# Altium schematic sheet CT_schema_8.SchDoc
size 274 x 160 mm
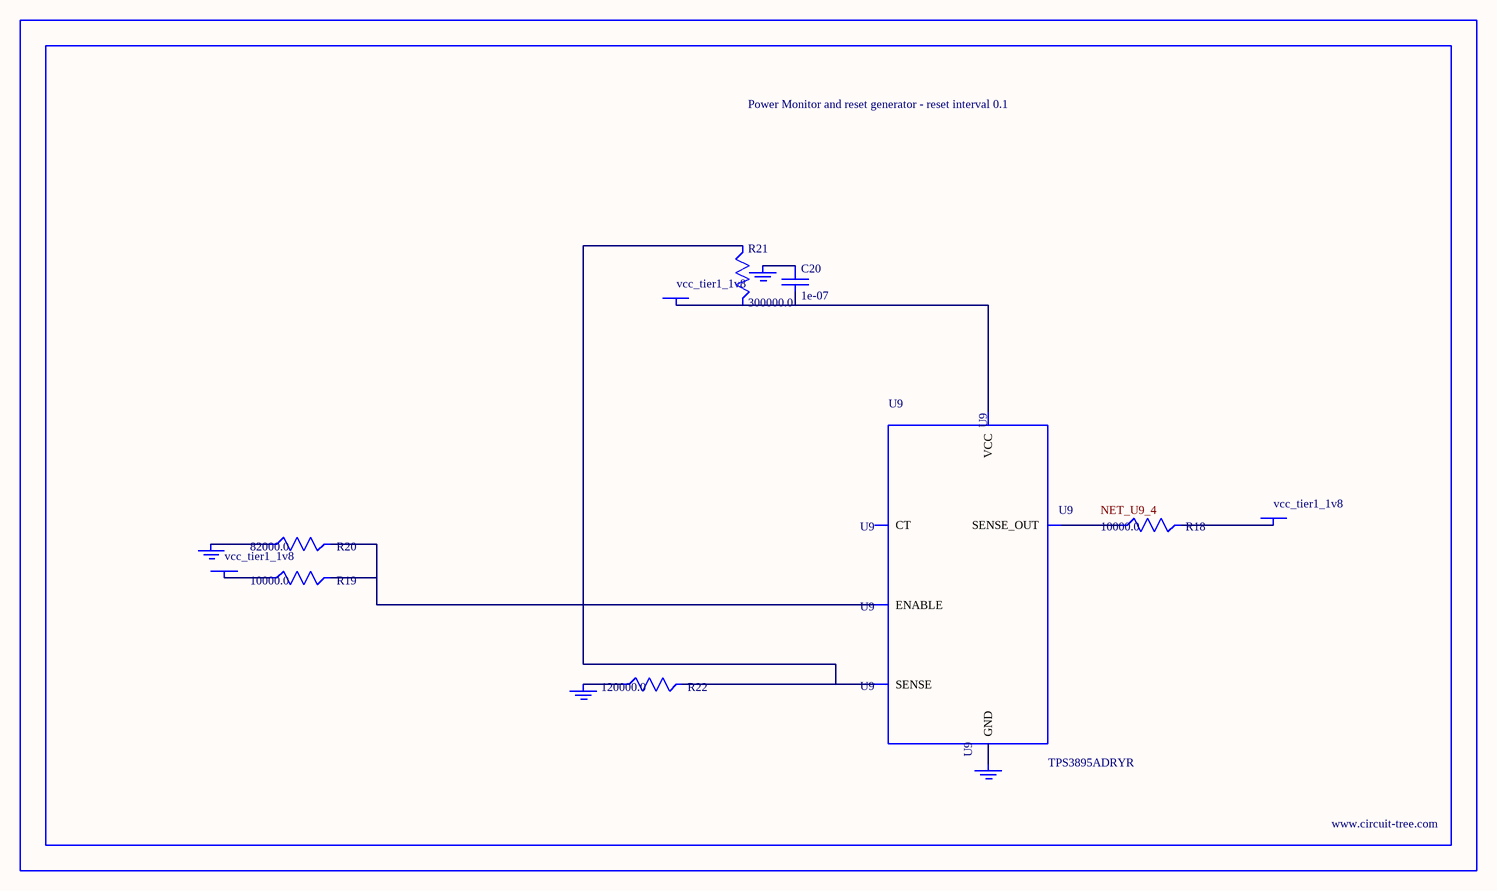
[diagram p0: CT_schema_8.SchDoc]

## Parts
BORDER7  (no value)
C20  1e-07  [C0402]
GND_INSTANCE_7_0  (no value)
GND_INSTANCE_7_1  (no value)
GND_INSTANCE_7_2  (no value)
GND_INSTANCE_7_3  (no value)
POWER_INSTANCE_7_0  vcc_tier1_1v8
POWER_INSTANCE_7_1  vcc_tier1_1v8
POWER_INSTANCE_7_2  vcc_tier1_1v8
R18  10000.0  [R0603]
R19  10000.0  [R0603]
R20  82000.0  [R0603]
R21  300000.0  [R0603]
R22  120000.0  [R0603]
U9  TPS3895ADRYR  [SON-6]

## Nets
NetC20_1: C20.1 GND_INSTANCE_7_2.0(GND)
NetC20_2: C20.2 POWER_INSTANCE_7_2.0(PWR) R21.2 U9.6(VCC)
NetGND_INSTANCE_7_0_0: GND_INSTANCE_7_0.0(GND) R20.1
NetGND_INSTANCE_7_1_0: GND_INSTANCE_7_1.0(GND) R22.1
NetGND_INSTANCE_7_3_0: GND_INSTANCE_7_3.0(GND) U9.2(GND)
NetPOWER_INSTANCE_7_0_0: POWER_INSTANCE_7_0.0(PWR) R19.1
NetPOWER_INSTANCE_7_1_0: POWER_INSTANCE_7_1.0(PWR) R18.2
NetR18_1: R18.1 U9.4(SENSE_OUT)
NetR19_2: R19.2 R20.2 U9.1(ENABLE)
NetR21_1: R21.1 R22.2 U9.3(SENSE)

Not connected (* = marked no-connect by the designer): U9 5(CT)

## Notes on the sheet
- Labels drawn without touching a wire or pin: NET_U9_4

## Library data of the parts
BORDER7 = BORDER_PAGE7
C20 = C0402C104K3RACTU
GND_INSTANCE_7_0-GND_INSTANCE_7_3 = GND
POWER_INSTANCE_7_0-POWER_INSTANCE_7_2 = PWR
R18 R19 = RC0603JR-0710KL
R20 = RC0603JR-0782KL
R21 = RC0603JR-07300KL
R22 = RC0603JR-07120KL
